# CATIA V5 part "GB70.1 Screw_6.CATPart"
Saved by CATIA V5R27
Part number: 螺钉_PowerCopy_1
Bounding box of the stored display mesh (mm): x -5 to 5, y -4.99 to 4.99, z -6 to 45
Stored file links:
  E:\资料\Catia超级副本\GB 70.1螺钉_带平垫\GB70.1 Screw_6.CATPart
  E:\资料\Catia超级副本\GB70.1 螺钉\DesignTable.xlsx
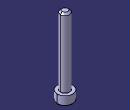
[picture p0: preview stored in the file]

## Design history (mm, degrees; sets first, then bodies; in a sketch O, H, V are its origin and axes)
Parameters
  `圆柱头直径` = 10 mm {design table}
  `圆柱头厚度` = 6 mm {design table}
  s = 5 mm {design table}
  t = 3 mm {design table}
  v = 0.6 mm {design table}
  b = 1.2 mm {design table}
  `公称直径` = 6 mm {design table}
  `螺钉长度` = 45 mm {design table}
AxisSystem1: origin (0, 0, 0), X (1, 0, 0), Y (0, 1, 0), Z (0, 0, 1)
Set1 "定位元素"
  Plane1: type Normal, Curve Line1, RefPoint Point1, Ratio 0
  Point1: (0, 0, 0), in AxisSystem1
Body1 (main body)
  Sketch1 on Plane1, origin (0, 0, 0), H (1, 0, 0), V (0, 1, 0)
    circle A1 centre (0, 0) radius 5
    radius A1 = 5 {= `圆柱头直径` /2}
  Pad1: profile Sketch1, direction (0, 0, -1), length 6 {= `圆柱头厚度`}
  Fillet1: radius 0.6 {= v}, on end face of Pad1
  Sketch2 on Plane1, origin (0, 0, 0), H (1, 0, 0), V (0, 1, 0)
    circle A1 centre (0, 0) radius 3
    radius A1 = 3 {= `公称直径` /2}
  Pad2: profile Sketch2, direction (0, 0, 1), length 45 {= `螺钉长度`}
  Chamfer1: length 1.2 {= b}, angle 45, on end face of Pad2
  Set2
    Line1: type PtDir, RefPoint Point1, Direction (0, 0, 1), Start 0, End 20
  Sketch3 on end face of Pad1, origin (0, 0, -6), H (1, 0, 0), V (0, -1, 0)
    point P1 (0, 0)
    point P2 (2.5, 0)
    construction circle A1 centre (0, 0) radius 2.8868
    construction circle A2 centre (0, 0) radius 2.5
    point P3 (2.5, -1.4434)
    point P4 (2.5, 1.4434)
    point P5 (0, 2.8868)
    point P6 (-2.5, 1.4434)
    point P7 (-2.5, -1.4434)
    point P8 (0, -2.8868)
    line L1 (2.5, -1.4434) -> (2.5, 1.4434)
    line L2 (2.5, 1.4434) -> (0, 2.8868)
    line L3 (0, 2.8868) -> (-2.5, 1.4434)
    line L4 (-2.5, 1.4434) -> (-2.5, -1.4434)
    line L5 (-2.5, -1.4434) -> (0, -2.8868)
    line L6 (0, -2.8868) -> (2.5, -1.4434)
    construction line L7 (0, 0) -> (2.5, 0)
    reference projected point E1 (0, 0) from axis of face of Pad1 from Sketch1.A1
    distance L1 L4 = 5 {= s}
    coincidence: A1 P3, A1 P4, A1 P5, A1 P6, A1 P7, A1 P8, P1 H, P1 E1
    tangency: A2 L1, A2 L2, A2 L3, A2 L4, A2 L5, A2 L6
    midpoint: P2 L1
    horizontal: L7 H
  Pocket1: profile Sketch3, direction (0, 0, 1), length 3 {= t}
Relations
  design table "GB70.1 螺钉参数表", configuration 66, drives `圆柱头直径`, `圆柱头厚度`, s, t, v, b, `公称直径`, `螺钉长度`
